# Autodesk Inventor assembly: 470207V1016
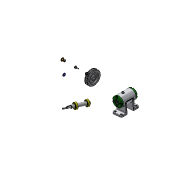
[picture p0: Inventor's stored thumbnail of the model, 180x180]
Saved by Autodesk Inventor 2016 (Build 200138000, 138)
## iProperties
Created: 2017-02
Part Number: 470207V1016
Material: 일반
Document SubType Name: Assembly
Designer: H
Author: H
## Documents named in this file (16)
- C:\Users\CAMTIC\Desktop\470207V1016\470207V1016.iam
- C:\Users\CAMTIC\Desktop\470207V1016\470207V1016.ipt
- C:\Users\CAMTIC\Desktop\470207V1016\V벨트풀리.ipt
- C:\Users\CAMTIC\Desktop\470207V1016\너트 M 8.ipt
- C:\Users\CAMTIC\Desktop\470207V1016\니플 M 6 x 0.75.ipt
- C:\Users\CAMTIC\Desktop\470207V1016\뒤커버.ipt
- C:\Users\CAMTIC\Desktop\470207V1016\베어링 15 x 32 x 9.ipt
- C:\Users\CAMTIC\Desktop\470207V1016\볼트 M 6 x 8.ipt
- C:\Users\CAMTIC\Desktop\470207V1016\볼트 M4 x 12.ipt
- C:\Users\CAMTIC\Desktop\470207V1016\스프링와셔 8.ipt
- C:\Users\CAMTIC\Desktop\470207V1016\앞커버.ipt
- C:\Users\CAMTIC\Desktop\470207V1016\오일 실 15 25 7.ipt
- C:\Users\CAMTIC\Desktop\470207V1016\와셔 6x11.5.ipt
- C:\Users\CAMTIC\Desktop\470207V1016\와셔 8x17.ipt
- C:\Users\CAMTIC\Desktop\470207V1016\축.ipt
- C:\Users\CAMTIC\Desktop\470207V1016\키 3 x 3 x 12.ipt
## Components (5 placed, 4 different names)
1. 470207V1016:1
2. V벨트풀리:1
3. KS B 2023 6002 - 15 x 32 x 9:1
4. ISO 4762 M4 x 12:1
5. KS B 2023 6002 - 15 x 32 x 9:2
